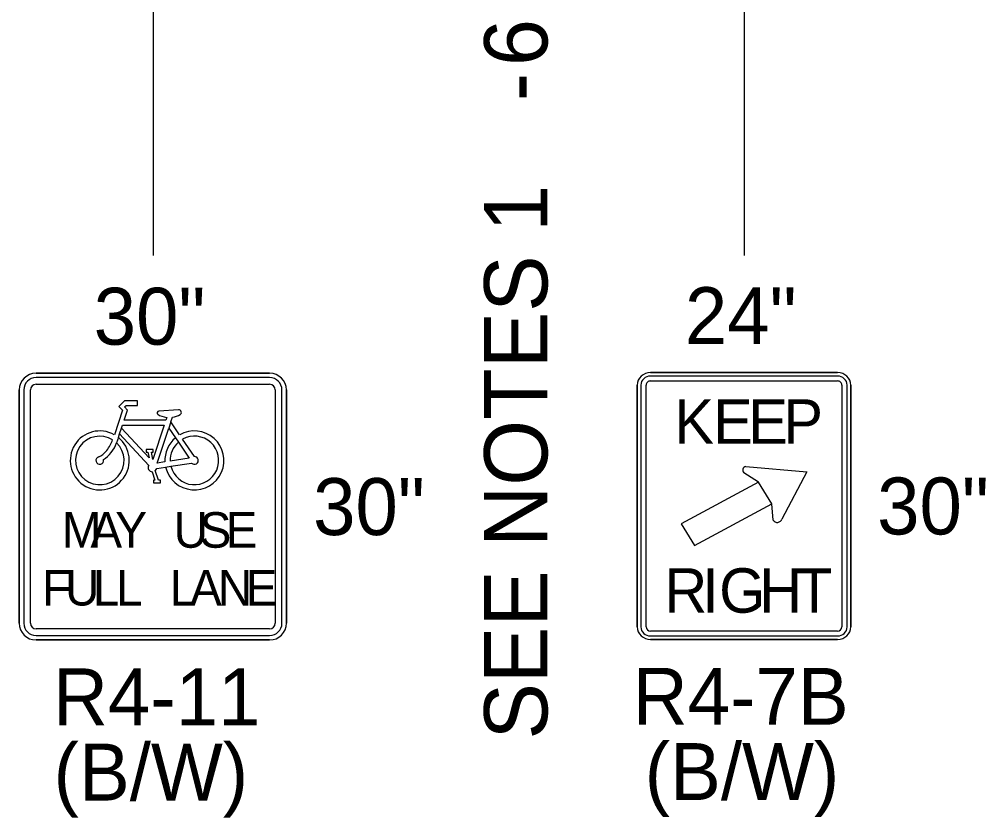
# Model space of a CAD drawing. Extents: x 99982 to 100176, y 99905 to 100011.
# Drawn here: x 100010.522 to 100011.744, y 99915.128 to 99916.138 of the extents above; entities that cross this region are included whole.
import ezdxf

# ---------------------------------------------------------------- set-up
doc = ezdxf.new("R2010")
doc.units = 0
for name, color, linetype in [('TR_SN_ConstructionSigns', 7, 'Continuous'), ('TR_WZ_WorkZoneDetails', 7, 'Continuous'), ('TR_WZ_WorkZoneTextCurrent', 7, 'Continuous')]:
    doc.layers.add(name, color=color, linetype=linetype)

msp = doc.modelspace()

# ---------------------------------------------------------------- linework, layer by layer
at = {"layer": 'TR_SN_ConstructionSigns'}
for p, q in [((100010.5435, 99915.6906), (100010.8388, 99915.6906)), ((100010.8388, 99915.6906), (100010.5435, 99915.6906)), ((100010.8388, 99915.6906), (100010.5435, 99915.6906)), ((100011.3202, 99915.6913), (100011.5565, 99915.6913)), ((100011.5565, 99915.6913), (100011.3202, 99915.6913)), ((100011.5565, 99915.6869), (100011.3202, 99915.6869)), ((100010.8388, 99915.6849), (100010.5435, 99915.6849)), ((100010.5435, 99915.6765), (100010.8388, 99915.6765)), ((100011.3034, 99915.3696), (100011.3034, 99915.6755)), ((100011.3034, 99915.6755), (100011.3034, 99915.3696)), ((100011.308, 99915.6755), (100011.308, 99915.3696)), ((100011.3146, 99915.3696), (100011.3146, 99915.6755)), ((100011.3202, 99915.6808), (100011.5565, 99915.6808)), ((100011.5621, 99915.6755), (100011.5621, 99915.3696)), ((100011.5687, 99915.3696), (100011.5687, 99915.6755)), ((100011.5734, 99915.6755), (100011.5734, 99915.3696)), ((100011.5734, 99915.3696), (100011.5734, 99915.6755)), ((100010.5224, 99915.3742), (100010.5224, 99915.6695)), ((100010.5224, 99915.6695), (100010.5224, 99915.3742)), ((100010.5224, 99915.6695), (100010.5224, 99915.3742)), ((100010.528, 99915.6695), (100010.528, 99915.3742)), ((100010.5365, 99915.3742), (100010.5365, 99915.6695)), ((100010.8458, 99915.6695), (100010.8458, 99915.3742)), ((100010.8543, 99915.3742), (100010.8543, 99915.6695)), ((100010.8599, 99915.6695), (100010.8599, 99915.3742)), ((100010.8599, 99915.3742), (100010.8599, 99915.6695)), ((100010.8599, 99915.3742), (100010.8599, 99915.6695)), ((100010.6552, 99915.6554), (100010.6482, 99915.6484)), ((100010.6716, 99915.6554), (100010.6552, 99915.6554)), ((100010.6716, 99915.6499), (100010.6716, 99915.6554)), ((100010.6528, 99915.6438), (100010.6425, 99915.6127)), ((100010.6482, 99915.6484), (100010.6528, 99915.6438)), ((100010.6551, 99915.6313), (100010.6592, 99915.6438)), ((100010.6553, 99915.6478), (100010.6574, 99915.6499)), ((100010.6592, 99915.6438), (100010.6553, 99915.6478)), ((100010.6574, 99915.6499), (100010.6716, 99915.6499)), ((100010.7235, 99915.6442), (100010.6987, 99915.6425)), ((100010.7077, 99915.6313), (100010.6551, 99915.6313)), ((100010.7088, 99915.6347), (100010.7077, 99915.6313)), ((100010.7138, 99915.629), (100010.7112, 99915.6211)), ((100010.7138, 99915.629), (100010.7158, 99915.6348)), ((100010.725, 99915.6125), (100010.7138, 99915.629)), ((100010.6477, 99915.6091), (100010.6492, 99915.6138)), ((100010.6492, 99915.6138), (100010.6516, 99915.6209)), ((100010.6492, 99915.6138), (100010.6859, 99915.574)), ((100010.6516, 99915.6209), (100010.6529, 99915.6247)), ((100010.6863, 99915.5833), (100010.6516, 99915.6209)), ((100010.6529, 99915.6247), (100010.7055, 99915.6247)), ((100010.7055, 99915.6247), (100010.6911, 99915.5814)), ((100010.6965, 99915.5769), (100010.7112, 99915.6211)), ((100010.7112, 99915.6211), (100010.7196, 99915.6087)), ((100010.6477, 99915.6091), (100010.6454, 99915.6023)), ((100010.7196, 99915.6087), (100010.7234, 99915.6032)), ((100010.7234, 99915.6032), (100010.7372, 99915.5829)), ((100010.7436, 99915.5851), (100010.7287, 99915.607)), ((100010.6915, 99915.594), (100010.6828, 99915.594)), ((100010.6849, 99915.5907), (100010.6863, 99915.5833)), ((100010.6911, 99915.5814), (100010.6894, 99915.5907)), ((100010.6894, 99915.5907), (100010.6915, 99915.5907)), ((100010.6915, 99915.5907), (100010.6915, 99915.594)), ((100010.7064, 99915.5783), (100010.6965, 99915.5769)), ((100010.7372, 99915.5829), (100010.713, 99915.5793)), ((100010.6902, 99915.5659), (100010.6938, 99915.5551)), ((100010.6984, 99915.5551), (100010.6943, 99915.5673)), ((100010.696, 99915.5702), (100010.7073, 99915.5718)), ((100010.7073, 99915.5718), (100010.7139, 99915.5728)), ((100010.7139, 99915.5728), (100010.7402, 99915.5767)), ((100011.4567, 99915.5529), (100011.4382, 99915.5647)), ((100011.4407, 99915.5725), (100011.5177, 99915.5656)), ((100011.5177, 99915.5656), (100011.4863, 99915.506)), ((100010.6938, 99915.5551), (100010.692, 99915.5551)), ((100010.692, 99915.5551), (100010.692, 99915.5518)), ((100010.7007, 99915.5551), (100010.6984, 99915.5551)), ((100010.7007, 99915.5518), (100010.7007, 99915.5551)), ((100011.4567, 99915.5529), (100011.359, 99915.5)), ((100011.4736, 99915.5255), (100011.4567, 99915.5529)), ((100011.4736, 99915.5255), (100011.4567, 99915.5529)), ((100011.4567, 99915.5529), (100011.4567, 99915.5529)), ((100010.692, 99915.5518), (100010.7007, 99915.5518)), ((100011.3758, 99915.4726), (100011.4736, 99915.5255)), ((100011.4752, 99915.5045), (100011.4736, 99915.5255)), ((100011.4736, 99915.5255), (100011.4736, 99915.5255)), ((100011.359, 99915.5), (100011.3758, 99915.4726)), ((100010.8388, 99915.3671), (100010.5435, 99915.3671)), ((100010.5435, 99915.3587), (100010.8388, 99915.3587)), ((100011.5565, 99915.3644), (100011.3202, 99915.3644)), ((100011.3202, 99915.3582), (100011.5565, 99915.3582)), ((100010.8388, 99915.3531), (100010.5435, 99915.3531)), ((100010.5435, 99915.3531), (100010.8388, 99915.3531)), ((100010.5435, 99915.3531), (100010.8388, 99915.3531)), ((100011.5565, 99915.3538), (100011.3202, 99915.3538)), ((100011.3202, 99915.3538), (100011.5565, 99915.3538))]:
    msp.add_line(p, q, dxfattribs=at)
msp.add_lwpolyline([(100010.6828, 99915.594), (100010.6828, 99915.5907), (100010.6849, 99915.5907)], dxfattribs=at)
for centre, radius, start, end in [((100010.5435, 99915.6695), 0.0211, 90, 180), ((100010.5435, 99915.6695), 0.0211, 90, 180), ((100010.5435, 99915.6695), 0.0211, 90, 180), ((100010.8388, 99915.6695), 0.0211, 0, 90), ((100010.8388, 99915.6695), 0.0211, 0, 90), ((100010.8388, 99915.6695), 0.0211, 0, 90), ((100010.5435, 99915.6695), 0.0155, 90, 180), ((100010.5435, 99915.6695), 0.00703, 90, 180), ((100010.8388, 99915.6695), 0.0155, 0, 90), ((100010.8388, 99915.6695), 0.00703, 0, 90), ((100010.6987, 99915.6403), 0.00219, 89.3854, 243.6828), ((100010.7239, 99915.6409), 0.00329, 294.5519, 96.4128), ((100010.6241, 99915.5802), 0.0373, 60.5529, 50.868), ((100010.7437, 99915.5802), 0.0373, 192.9622, 119.9648), ((100010.6241, 99915.5802), 0.0307, 58.1532, 46.1649), ((100010.7437, 99915.5802), 0.0373, 130.0889, 182.8379), ((100010.7437, 99915.5802), 0.0307, 131.3616, 181.6359), ((100010.7437, 99915.5802), 0.0307, 193.937, 119.0598), ((100010.6241, 99915.5802), 0.00493, 105.257, 14.3233), ((100010.7437, 99915.5802), 0.00493, 225.1095, 90.4672), ((100010.6907, 99915.5714), 0.00548, 151.1744, 264.8566), ((100010.6907, 99915.5714), 0.00548, 312.0053, 347.2932), ((100010.5435, 99915.3742), 0.0211, 180, 270), ((100010.5435, 99915.3742), 0.0211, 180, 270), ((100010.5435, 99915.3742), 0.0211, 180, 270), ((100010.5435, 99915.3742), 0.0155, 180, 270), ((100010.5435, 99915.3742), 0.00703, 180, 270), ((100010.8388, 99915.3742), 0.0211, 270, 0), ((100010.8388, 99915.3742), 0.0211, 270, 0), ((100010.8388, 99915.3742), 0.0155, 270, 0), ((100010.8388, 99915.3742), 0.00703, 270, 0), ((100010.8388, 99915.3742), 0.0211, 270, 0)]:
    msp.add_arc(centre, radius, start, end, dxfattribs=at)
for centre, major_axis, ratio, start_param, end_param in [((100011.3202, 99915.6755), (-0.0169, 0), 0.9375, 4.712389, 6.283185), ((100011.3202, 99915.6755), (-0.0169, 0), 0.9375, 4.712389, 6.283185), ((100011.3202, 99915.6755), (0.0122, 0), 0.9375, 1.570796, 3.141593), ((100011.5565, 99915.6755), (-0.0169, 0), 0.9375, 3.141593, 4.712389), ((100011.5565, 99915.6755), (-0.0169, 0), 0.9375, 3.141593, 4.712389), ((100011.5565, 99915.6755), (0.0122, 0), 0.9375, 0, 1.570796), ((100011.3202, 99915.6755), (0.00563, 0), 0.9375, 1.570796, 3.141593), ((100011.5565, 99915.6755), (0.00562, 0), 0.9375, 6.283185, 7.853982), ((100010.7118, 99915.6455), (-0.0186, 0), 0.588235, 0.686048, 1.410588), ((100010.7118, 99915.6455), (-0.0186, 0), 0.588235, 1.786993, 2.401245), ((100010.629, 99915.6009), (-0.0105, -0.0158), 0.413554, 0.494612, 2.170849), ((100010.629, 99915.6009), (-0.014, -0.021), 0.55814, 0.868091, 1.989998), ((100011.4415, 99915.568), (0.00485, -0.00001), 0.937492, 1.73335, 3.955171), ((100011.4804, 99915.5075), (0.00607, -0.00002), 0.9368, 3.700197, 6.020834), ((100011.3202, 99915.3696), (0.0169, 0), 0.9375, 3.141593, 4.712389), ((100011.3202, 99915.3696), (0.0169, 0), 0.9375, 3.141593, 4.712389), ((100011.3202, 99915.3696), (0.0122, 0), 0.9375, 3.141593, 4.712389), ((100011.3202, 99915.3696), (0.00563, 0), 0.9375, 3.141593, 4.712389), ((100011.5565, 99915.3696), (0.0169, 0), 0.9375, 4.712389, 6.283185), ((100011.5565, 99915.3696), (0.0122, 0), 0.9375, 4.712389, 6.283185), ((100011.5565, 99915.3696), (0.00562, 0), 0.9375, 4.712389, 6.283185), ((100011.5565, 99915.3696), (0.0169, 0), 0.9375, 4.712389, 6.283185)]:
    msp.add_ellipse(centre, major_axis=major_axis, ratio=ratio, start_param=start_param, end_param=end_param, dxfattribs=at)
at = {"layer": 'TR_WZ_WorkZoneDetails'}
for p, q in [((100011.4384, 99916.2797), (100011.4384, 99915.8393)), ((100010.6914, 99916.2577), (100010.6914, 99915.8393))]:
    msp.add_line(p, q, dxfattribs=at)

# ---------------------------------------------------------------- texts
at = {"layer": 'TR_SN_ConstructionSigns'}
for s, p in [('30"', (100010.6164, 99915.7266)), ('24"', (100011.3636, 99915.7273)), ('30"', (100010.8937, 99915.4858)), ('30"', (100011.6066, 99915.4866)), ('R4-11', (100010.5649, 99915.2451)), ('R4-7B', (100011.2977, 99915.2458)), ('(B/W)', (100010.5657, 99915.15)), ('(B/W)', (100011.3128, 99915.1507))]:
    msp.add_text(s, height=0.072, rotation=360, dxfattribs=at).set_placement(p)
for s, height, p in [('K', 0.0562, (100011.3503, 99915.6013)), ('E', 0.0562, (100011.3993, 99915.6013)), ('E', 0.0562, (100011.4437, 99915.6013)), ('P', 0.0562, (100011.4881, 99915.6013)), ('M', 0.045, (100010.5762, 99915.4698)), ('A', 0.045, (100010.6122, 99915.4698)), ('Y', 0.045, (100010.6437, 99915.4698)), ('U', 0.045, (100010.7175, 99915.4698)), ('S', 0.045, (100010.7503, 99915.4698)), ('E', 0.045, (100010.7832, 99915.4698)), ('R', 0.0562, (100011.3377, 99915.3876)), ('I', 0.0562, (100011.3855, 99915.3876)), ('G', 0.0562, (100011.4069, 99915.3876)), ('H', 0.0562, (100011.4575, 99915.3876)), ('T', 0.0562, (100011.5042, 99915.3876)), ('F', 0.045, (100010.551, 99915.3967)), ('U', 0.045, (100010.5802, 99915.3967)), ('L', 0.045, (100010.6153, 99915.3967)), ('L', 0.045, (100010.6446, 99915.3967)), ('L', 0.045, (100010.7125, 99915.3967)), ('A', 0.045, (100010.7382, 99915.3967)), ('N', 0.045, (100010.7733, 99915.3967)), ('E', 0.045, (100010.8084, 99915.3967))]:
    msp.add_text(s, height=height, dxfattribs=at).set_placement(p)
at = {"layer": 'TR_WZ_WorkZoneTextCurrent'}
for s, p in [('6', (100011.1899, 99916.079)), ('-', (100011.1899, 99916.0349)), ('SEE NOTES 1', (100011.1899, 99915.2272))]:
    msp.add_text(s, height=0.08, rotation=90, dxfattribs=at).set_placement(p)

doc.saveas('drawing.dxf')
